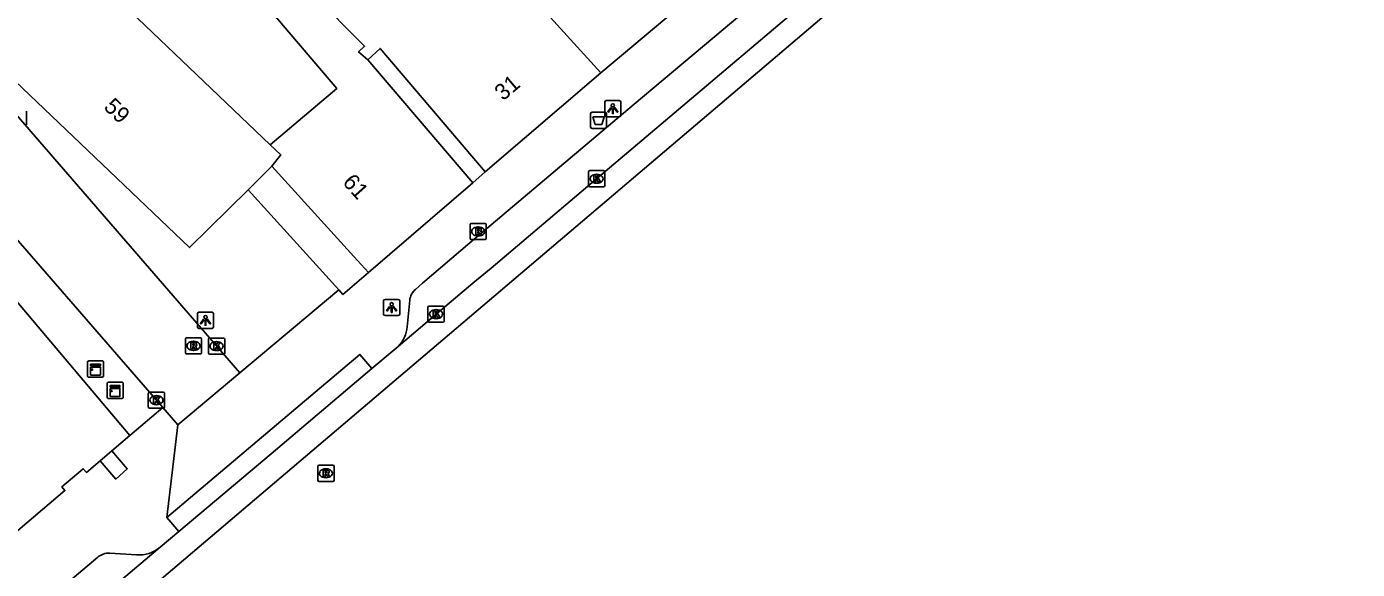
# Model space of a CAD drawing. Extents: x 161772 to 163123, y 383092 to 383917.
# Drawn here: x 162310.8 to 162393, y 383232.3 to 383265.9 of the extents above; entities that cross this region are included whole.
import ezdxf

# ---------------------------------------------------------------- set-up
doc = ezdxf.new("R2010")
doc.units = 0
for name, color, linetype in [('IMGEO_Afvalbak', 7, 'Continuous'), ('IMGEO_Brandkraan', 7, 'Continuous'), ('IMGEO_Kast', 7, 'Continuous'), ('IMGEO_Kolk', 7, 'Continuous'), ('IMGEO_Lichtpunt', 7, 'Continuous'), ('IMGEO_Pand', 7, 'Continuous'), ('IMGEO_Pand_nummerreeks', 7, 'Continuous'), ('IMGEO_Rijbaan_lokaal_gesloten', 7, 'Continuous'), ('IMGEO_Rioolput', 7, 'Continuous'), ('IMGEO_Voetpad_open', 7, 'Continuous')]:
    doc.layers.add(name, color=color, linetype=linetype)

msp = doc.modelspace()

# ---------------------------------------------------------------- linework, layer by layer
at = {"layer": 'IMGEO_Afvalbak'}
for p, q in [((162345.628, 383259.67), (162345.628, 383260.47)), ((162345.628, 383260.47), (162345.628, 383259.67)), ((162345.728, 383260.57), (162346.518, 383260.57)), ((162346.518, 383260.57), (162345.728, 383260.57)), ((162346.618, 383260.47), (162346.618, 383259.67)), ((162346.618, 383259.67), (162346.618, 383260.47)), ((162346.518, 383259.57), (162345.728, 383259.57)), ((162345.728, 383259.57), (162346.518, 383259.57))]:
    msp.add_line(p, q, dxfattribs=at)
msp.add_lwpolyline([(162345.771, 383260.284), (162346.475, 383260.284), (162346.326, 383259.814), (162345.92, 383259.814), (162345.771, 383260.284)], dxfattribs=at)
for centre, start, end in [((162345.728, 383260.47), 90, 180), ((162345.728, 383260.47), 90, 180), ((162346.518, 383260.47), 0, 90), ((162346.518, 383260.47), 360, 90), ((162345.728, 383259.67), 180, 270), ((162345.728, 383259.67), 180, 270), ((162346.518, 383259.67), 270, 0), ((162346.518, 383259.67), 270, 0)]:
    msp.add_arc(centre, 0.1, start, end, dxfattribs=at)
at = {"layer": 'IMGEO_Brandkraan'}
for p, q in [((162338.189, 383252.772), (162338.189, 383253.624)), ((162338.264, 383253.698), (162339.116, 383253.698)), ((162338.677, 383253.478), (162338.702, 383253.478)), ((162339.19, 383253.624), (162339.19, 383252.772)), ((162339.116, 383252.698), (162338.264, 383252.698)), ((162338.7, 383252.918), (162338.675, 383252.918))]:
    msp.add_line(p, q, dxfattribs=at)
for points in [[(162338.189, 383252.772), (162338.189, 383253.624)], [(162338.264, 383253.698), (162339.116, 383253.698)], [(162338.537, 383253.398), (162338.537, 383252.998), (162338.75, 383252.998)], [(162338.768, 383253.398), (162338.537, 383253.398)], [(162338.716, 383253.317), (162338.662, 383253.317), (162338.662, 383253.241)], [(162338.662, 383253.241), (162338.715, 383253.241)], [(162339.19, 383253.624), (162339.19, 383252.772)], [(162339.116, 383252.698), (162338.264, 383252.698)], [(162338.724, 383253.165), (162338.662, 383253.165), (162338.662, 383253.084)], [(162338.662, 383253.084), (162338.724, 383253.084)]]:
    msp.add_lwpolyline(points, dxfattribs=at)
for centre, radius, start, end in [((162338.266, 383253.622), 0.0765, 91.55205, 178.44795), ((162338.266, 383253.622), 0.0765, 91.55205, 178.44795), ((162338.717, 383253.279), 0.0379, 267.82845, 90.93552), ((162338.772, 383253.253), 0.145, 59.4692, 91.53667), ((162338.797, 383253.3), 0.0922, 285.51372, 58.15012), ((162339.114, 383253.622), 0.0765, 1.55205, 88.44795), ((162339.114, 383253.622), 0.0765, 1.55205, 88.44795), ((162338.266, 383252.774), 0.0765, 181.55205, 268.44795), ((162338.266, 383252.774), 0.0765, 181.55205, 268.44795), ((162338.725, 383253.124), 0.0404, 269.87594, 90.50774), ((162338.756, 383253.249), 0.251, 268.66757, 293.53466), ((162338.802, 383253.108), 0.105, 301.31148, 78.98903), ((162339.114, 383252.774), 0.0765, 271.55205, 358.44795), ((162339.114, 383252.774), 0.0765, 271.55205, 358.44795)]:
    msp.add_arc(centre, radius, start, end, dxfattribs=at)
for centre, major_axis, ratio, start_param, end_param in [((162338.676, 383253.198), (-0.387, 0.002), 0.722429, 4.712389, 7.853982), ((162338.701, 383253.198), (-0.39, 0.002), 0.717154, 1.570796, 4.712389)]:
    msp.add_ellipse(centre, major_axis=major_axis, ratio=ratio, start_param=start_param, end_param=end_param, dxfattribs=at)
at = {"layer": 'IMGEO_Kast'}
for p, q in [((162314.555, 383244.276), (162314.555, 383245.117)), ((162314.555, 383245.117), (162314.555, 383244.276)), ((162314.63, 383245.201), (162315.471, 383245.201)), ((162315.471, 383245.201), (162314.63, 383245.201)), ((162315.555, 383245.126), (162315.555, 383244.285)), ((162315.555, 383244.285), (162315.555, 383245.126)), ((162315.48, 383244.201), (162314.639, 383244.201)), ((162314.639, 383244.201), (162315.48, 383244.201)), ((162315.764, 383242.957), (162315.764, 383243.798)), ((162315.764, 383243.798), (162315.764, 383242.957)), ((162315.839, 383243.882), (162316.68, 383243.882)), ((162316.68, 383243.882), (162315.839, 383243.882)), ((162316.764, 383243.807), (162316.764, 383242.966)), ((162316.764, 383242.966), (162316.764, 383243.807)), ((162316.689, 383242.882), (162315.848, 383242.882)), ((162315.848, 383242.882), (162316.689, 383242.882))]:
    msp.add_line(p, q, dxfattribs=at)
for points in [[(162314.75, 383244.991), (162315.35, 383244.991), (162315.35, 383244.906), (162314.75, 383244.906), (162314.75, 383244.991)], [(162314.75, 383244.816), (162315.35, 383244.816), (162315.35, 383244.327), (162314.75, 383244.327), (162314.75, 383244.816)], [(162315.959, 383243.672), (162316.559, 383243.672), (162316.559, 383243.587), (162315.959, 383243.587), (162315.959, 383243.672)], [(162315.959, 383243.497), (162316.559, 383243.497), (162316.559, 383243.008), (162315.959, 383243.008), (162315.959, 383243.497)]]:
    msp.add_lwpolyline(points, dxfattribs=at)
for centre in [(162314.834, 383244.665), (162316.043, 383243.346)]:
    msp.add_circle(centre, 0.0377, dxfattribs=at)
for centre, start, end in [((162314.633, 383245.123), 92.4484, 184.28452), ((162314.633, 383245.123), 92.4484, 184.28452), ((162315.477, 383245.123), 2.4484, 94.28452), ((162315.477, 383245.123), 2.4484, 94.28452), ((162314.633, 383244.279), 182.4484, 274.28452), ((162314.633, 383244.279), 182.4484, 274.28452), ((162315.477, 383244.279), 272.4484, 4.28452), ((162315.477, 383244.279), 272.4484, 4.28452), ((162315.842, 383243.804), 92.4484, 184.28452), ((162315.842, 383243.804), 92.4484, 184.28452), ((162316.686, 383243.804), 2.4484, 94.28452), ((162316.686, 383243.804), 2.4484, 94.28452), ((162315.842, 383242.96), 182.4484, 274.28452), ((162315.842, 383242.96), 182.4484, 274.28452), ((162316.686, 383242.96), 272.4484, 4.28452), ((162316.686, 383242.96), 272.4484, 4.28452)]:
    msp.add_arc(centre, 0.0779, start, end, dxfattribs=at)
at = {"layer": 'IMGEO_Kolk'}
for p, q in [((162310.795, 383260.632), (162310.795, 383259.78)), ((162345.508, 383256.032), (162345.508, 383256.884)), ((162345.583, 383256.958), (162346.435, 383256.958)), ((162345.996, 383256.738), (162346.021, 383256.738)), ((162346.509, 383256.884), (162346.509, 383256.032)), ((162346.435, 383255.958), (162345.583, 383255.958)), ((162346.019, 383256.178), (162345.994, 383256.178)), ((162335.588, 383247.665), (162335.588, 383248.517)), ((162335.663, 383248.591), (162336.515, 383248.591)), ((162336.076, 383248.371), (162336.101, 383248.371)), ((162336.589, 383248.517), (162336.589, 383247.665)), ((162336.515, 383247.591), (162335.663, 383247.591)), ((162336.099, 383247.811), (162336.074, 383247.811)), ((162322.031, 383245.689), (162322.031, 383246.541)), ((162322.106, 383246.615), (162322.958, 383246.615)), ((162322.542, 383245.835), (162322.517, 383245.835)), ((162322.519, 383246.395), (162322.544, 383246.395)), ((162323.032, 383246.541), (162323.032, 383245.689)), ((162322.958, 383245.615), (162322.106, 383245.615)), ((162318.313, 383242.35), (162318.313, 383243.202)), ((162318.388, 383243.276), (162319.24, 383243.276)), ((162318.801, 383243.056), (162318.826, 383243.056)), ((162319.314, 383243.202), (162319.314, 383242.35)), ((162319.24, 383242.276), (162318.388, 383242.276)), ((162318.824, 383242.496), (162318.799, 383242.496))]:
    msp.add_line(p, q, dxfattribs=at)
for points in [[(162310.795, 383260.632), (162310.795, 383259.78)], [(162345.508, 383256.032), (162345.508, 383256.884)], [(162345.583, 383256.958), (162346.435, 383256.958)], [(162345.829, 383256.658), (162345.952, 383256.658), (162345.952, 383256.507), (162346.082, 383256.658), (162346.246, 383256.658), (162346.1, 383256.507), (162346.253, 383256.258), (162346.101, 383256.258), (162346.016, 383256.422), (162345.952, 383256.355), (162345.952, 383256.258), (162345.829, 383256.258), (162345.829, 383256.658)], [(162346.509, 383256.884), (162346.509, 383256.032)], [(162346.435, 383255.958), (162345.583, 383255.958)], [(162335.588, 383247.665), (162335.588, 383248.517)], [(162335.663, 383248.591), (162336.515, 383248.591)], [(162335.909, 383248.291), (162336.032, 383248.291), (162336.032, 383248.14), (162336.162, 383248.291), (162336.326, 383248.291), (162336.18, 383248.14), (162336.333, 383247.891), (162336.181, 383247.891), (162336.096, 383248.055), (162336.032, 383247.988), (162336.032, 383247.891), (162335.909, 383247.891), (162335.909, 383248.291)], [(162336.589, 383248.517), (162336.589, 383247.665)], [(162336.515, 383247.591), (162335.663, 383247.591)], [(162322.031, 383245.689), (162322.031, 383246.541)], [(162322.106, 383246.615), (162322.958, 383246.615)], [(162322.352, 383246.315), (162322.475, 383246.315), (162322.475, 383246.164), (162322.605, 383246.315), (162322.769, 383246.315), (162322.623, 383246.164), (162322.776, 383245.915), (162322.624, 383245.915), (162322.539, 383246.079), (162322.475, 383246.012), (162322.475, 383245.915), (162322.352, 383245.915), (162322.352, 383246.315)], [(162323.032, 383246.541), (162323.032, 383245.689)], [(162322.958, 383245.615), (162322.106, 383245.615)], [(162318.313, 383242.35), (162318.313, 383243.202)], [(162318.388, 383243.276), (162319.24, 383243.276)], [(162318.634, 383242.976), (162318.757, 383242.976), (162318.757, 383242.825), (162318.887, 383242.976), (162319.051, 383242.976), (162318.905, 383242.825), (162319.058, 383242.576), (162318.906, 383242.576), (162318.821, 383242.74), (162318.757, 383242.673), (162318.757, 383242.576), (162318.634, 383242.576), (162318.634, 383242.976)], [(162319.314, 383243.202), (162319.314, 383242.35)], [(162319.24, 383242.276), (162318.388, 383242.276)]]:
    msp.add_lwpolyline(points, dxfattribs=at)
for centre, start, end in [((162345.585, 383256.882), 91.55205, 178.44795), ((162345.585, 383256.882), 91.55205, 178.44795), ((162346.433, 383256.882), 1.55205, 88.44795), ((162346.433, 383256.882), 1.55205, 88.44795), ((162345.585, 383256.034), 181.55205, 268.44795), ((162345.585, 383256.034), 181.55205, 268.44795), ((162346.433, 383256.034), 271.55205, 358.44795), ((162346.433, 383256.034), 271.55205, 358.44795), ((162335.665, 383248.515), 91.55205, 178.44795), ((162335.665, 383248.515), 91.55205, 178.44795), ((162336.513, 383248.515), 1.55205, 88.44795), ((162336.513, 383248.515), 1.55205, 88.44795), ((162335.665, 383247.667), 181.55205, 268.44795), ((162335.665, 383247.667), 181.55205, 268.44795), ((162336.513, 383247.667), 271.55205, 358.44795), ((162336.513, 383247.667), 271.55205, 358.44795), ((162322.108, 383246.539), 91.55205, 178.44795), ((162322.108, 383246.539), 91.55205, 178.44795), ((162322.956, 383246.539), 1.55205, 88.44795), ((162322.956, 383246.539), 1.55205, 88.44795), ((162322.108, 383245.691), 181.55205, 268.44795), ((162322.108, 383245.691), 181.55205, 268.44795), ((162322.956, 383245.691), 271.55205, 358.44795), ((162322.956, 383245.691), 271.55205, 358.44795), ((162318.39, 383243.2), 91.55205, 178.44795), ((162318.39, 383243.2), 91.55205, 178.44795), ((162319.238, 383243.2), 1.55205, 88.44795), ((162319.238, 383243.2), 1.55205, 88.44795), ((162318.39, 383242.352), 181.55205, 268.44795), ((162318.39, 383242.352), 181.55205, 268.44795), ((162319.238, 383242.352), 271.55205, 358.44795), ((162319.238, 383242.352), 271.55205, 358.44795)]:
    msp.add_arc(centre, 0.0765, start, end, dxfattribs=at)
for centre, major_axis, ratio, start_param, end_param in [((162345.995, 383256.458), (-0.387, 0.002), 0.722429, 4.712389, 7.853982), ((162346.02, 383256.458), (-0.39, 0.002), 0.717154, 1.570796, 4.712389), ((162336.075, 383248.091), (-0.387, 0.002), 0.722429, 4.712389, 7.853982), ((162336.1, 383248.091), (-0.39, 0.002), 0.717154, 1.570796, 4.712389), ((162322.518, 383246.115), (-0.387, 0.002), 0.722429, 4.712389, 7.853982), ((162322.543, 383246.115), (-0.39, 0.002), 0.717154, 1.570796, 4.712389), ((162318.8, 383242.776), (-0.387, 0.002), 0.722429, 4.712389, 7.853982), ((162318.825, 383242.776), (-0.39, 0.002), 0.717154, 1.570796, 4.712389)]:
    msp.add_ellipse(centre, major_axis=major_axis, ratio=ratio, start_param=start_param, end_param=end_param, dxfattribs=at)
at = {"layer": 'IMGEO_Lichtpunt'}
for p, q in [((162346.508, 383261.193), (162346.508, 383260.386)), ((162346.508, 383261.193), (162346.508, 383260.386)), ((162347.41, 383261.288), (162346.602, 383261.288)), ((162347.41, 383261.288), (162346.602, 383261.288)), ((162347.504, 383260.386), (162347.504, 383261.193)), ((162347.504, 383260.386), (162347.504, 383261.193)), ((162346.602, 383260.292), (162347.41, 383260.292)), ((162346.602, 383260.292), (162347.41, 383260.292)), ((162332.845, 383248.905), (162332.845, 383248.098)), ((162332.845, 383248.905), (162332.845, 383248.098)), ((162333.747, 383249), (162332.939, 383249)), ((162333.747, 383249), (162332.939, 383249)), ((162333.841, 383248.098), (162333.841, 383248.905)), ((162333.841, 383248.098), (162333.841, 383248.905)), ((162321.349, 383248.109), (162321.349, 383247.302)), ((162321.349, 383248.109), (162321.349, 383247.302)), ((162322.251, 383248.204), (162321.443, 383248.204)), ((162322.251, 383248.204), (162321.443, 383248.204)), ((162322.345, 383247.302), (162322.345, 383248.109)), ((162322.345, 383247.302), (162322.345, 383248.109)), ((162332.939, 383248.004), (162333.747, 383248.004)), ((162332.939, 383248.004), (162333.747, 383248.004)), ((162321.443, 383247.208), (162322.251, 383247.208)), ((162321.443, 383247.208), (162322.251, 383247.208))]:
    msp.add_line(p, q, dxfattribs=at)
for points in [[(162346.882, 383260.857), (162346.921, 383260.829), (162346.733, 383260.567), (162346.695, 383260.594), (162346.882, 383260.857)], [(162346.984, 383260.809), (162347.031, 383260.809), (162347.031, 383260.487), (162346.984, 383260.487), (162346.984, 383260.809)], [(162347.094, 383260.829), (162347.132, 383260.856), (162347.319, 383260.594), (162347.28, 383260.566), (162347.094, 383260.829)], [(162333.219, 383248.569), (162333.258, 383248.541), (162333.07, 383248.279), (162333.032, 383248.306), (162333.219, 383248.569)], [(162333.321, 383248.521), (162333.368, 383248.521), (162333.368, 383248.199), (162333.321, 383248.199), (162333.321, 383248.521)], [(162333.431, 383248.541), (162333.469, 383248.568), (162333.656, 383248.306), (162333.617, 383248.278), (162333.431, 383248.541)], [(162321.723, 383247.773), (162321.762, 383247.745), (162321.574, 383247.483), (162321.536, 383247.51), (162321.723, 383247.773)], [(162321.825, 383247.725), (162321.872, 383247.725), (162321.872, 383247.403), (162321.825, 383247.403), (162321.825, 383247.725)], [(162321.935, 383247.745), (162321.973, 383247.772), (162322.16, 383247.51), (162322.121, 383247.482), (162321.935, 383247.745)]]:
    msp.add_lwpolyline(points, dxfattribs=at)
for centre in [(162347.007, 383260.991), (162333.344, 383248.703), (162321.848, 383247.907)]:
    msp.add_circle(centre, 0.0994, dxfattribs=at)
for centre, start, end in [((162346.602, 383261.193), 90, 180), ((162346.602, 383261.193), 90, 180), ((162347.41, 383261.193), 0, 90), ((162347.41, 383261.193), 0, 90), ((162346.602, 383260.386), 180, 270), ((162346.602, 383260.386), 180, 270), ((162347.41, 383260.386), 270, 0), ((162347.41, 383260.386), 270, 360), ((162332.939, 383248.905), 90, 180), ((162332.939, 383248.905), 90, 180), ((162333.747, 383248.905), 0, 90), ((162333.747, 383248.905), 0, 90), ((162321.443, 383248.109), 90, 180), ((162321.443, 383248.109), 90, 180), ((162322.251, 383248.109), 0, 90), ((162322.251, 383248.109), 0, 90), ((162332.939, 383248.098), 180, 270), ((162332.939, 383248.098), 180, 270), ((162333.747, 383248.098), 270, 0), ((162333.747, 383248.098), 270, 360), ((162321.443, 383247.302), 180, 270), ((162321.443, 383247.302), 180, 270), ((162322.251, 383247.302), 270, 0), ((162322.251, 383247.302), 270, 360)]:
    msp.add_arc(centre, 0.0946, start, end, dxfattribs=at)
at = {"layer": 'IMGEO_Pand'}
for points in [[(162346.265, 383262.997), (162338.57, 383271.481), (162338.004, 383271.019), (162333.008, 383275.992)], [(162325.846, 383258.547), (162329.957, 383262.04), (162323.454, 383269.69), (162325.199, 383271.174), (162325.303, 383271.069)], [(162331.866, 383263.812), (162331.304, 383264.297), (162331.67, 383264.649), (162325.303, 383271.069)], [(162312.965, 383269.713), (162313.561, 383270.296), (162325.846, 383258.547)], [(162351.614, 383267.518), (162346.265, 383262.997)], [(162324.476, 383255.781), (162320.866, 383252.207), (162308.268, 383264.195)], [(162331.866, 383263.812), (162332.636, 383264.517), (162339.126, 383256.895)], [(162338.354, 383256.203), (162331.866, 383263.812)], [(162346.265, 383262.997), (162339.126, 383256.895)], [(162325.846, 383258.547), (162326.5, 383257.928), (162325.949, 383257.238)], [(162325.949, 383257.238), (162324.476, 383255.781)], [(162331.911, 383250.664), (162331.007, 383251.661), (162325.949, 383257.238)], [(162338.354, 383256.203), (162331.911, 383250.664)], [(162307.174, 383252.434), (162317.179, 383240.601)], [(162316.056, 383239.645), (162317.179, 383240.601)], [(162315.334, 383239.031), (162316.056, 383239.645)], [(162305.188, 383230.428), (162308.505, 383233.243), (162308.311, 383233.472), (162309.639, 383234.596), (162309.833, 383234.367), (162313.158, 383237.185), (162312.964, 383237.414), (162314.291, 383238.537), (162314.486, 383238.309), (162315.334, 383239.031)]]:
    msp.add_lwpolyline(points, dxfattribs=at)
at = {"layer": 'IMGEO_Rijbaan_lokaal_gesloten'}
for points in [[(162501.18, 383386.596), (162499.827, 383385.459), (162477.128, 383365.985), (162459.036, 383350.651), (162175.227, 383109.464), (162171.607, 383105.25), (162169.364, 383100.909), (162168.706, 383099.067), (162168.602, 383098.586)], [(162333.755, 383246.101), (162336.091, 383248.087), (162338.371, 383250), (162339.489, 383250.937), (162346.009, 383256.458), (162358.661, 383267.166), (162361.825, 383269.852), (162371.447, 383277.945), (162376.27, 383282.045), (162386.657, 383290.883), (162388.29, 383292.272), (162389.114, 383292.973)], [(162332.127, 383244.723), (162333.493, 383245.878), (162333.755, 383246.101)], [(162320.2, 383234.655), (162325.904, 383239.465), (162332.127, 383244.723)], [(162320.2, 383234.655), (162319.047, 383233.682)], [(162276.765, 383198.05), (162277.016, 383198.26), (162285.931, 383205.773), (162293.943, 383212.532), (162301.935, 383219.268), (162309.075, 383225.29), (162316.264, 383231.344), (162319.047, 383233.682)]]:
    msp.add_lwpolyline(points, dxfattribs=at)
at = {"layer": 'IMGEO_Rioolput'}
for p, q in [((162320.606, 383245.707), (162320.606, 383246.559)), ((162320.681, 383246.633), (162321.533, 383246.633)), ((162321.117, 383245.853), (162321.092, 383245.853)), ((162321.094, 383246.413), (162321.119, 383246.413)), ((162321.607, 383246.559), (162321.607, 383245.707)), ((162321.533, 383245.633), (162320.681, 383245.633)), ((162328.786, 383237.83), (162328.786, 383238.682)), ((162328.861, 383238.756), (162329.713, 383238.756)), ((162329.274, 383238.536), (162329.299, 383238.536)), ((162329.787, 383238.682), (162329.787, 383237.83)), ((162329.713, 383237.756), (162328.861, 383237.756)), ((162329.297, 383237.976), (162329.272, 383237.976))]:
    msp.add_line(p, q, dxfattribs=at)
for points in [[(162320.606, 383245.707), (162320.606, 383246.559)], [(162320.681, 383246.633), (162321.533, 383246.633)], [(162321.195, 383246.331), (162320.943, 383246.333), (162320.943, 383245.933)], [(162320.943, 383245.933), (162321.067, 383245.933), (162321.067, 383246.095), (162321.078, 383246.095)], [(162321.121, 383246.252), (162321.067, 383246.252), (162321.067, 383246.171)], [(162321.067, 383246.171), (162321.119, 383246.171)], [(162321.125, 383246.066), (162321.196, 383245.933), (162321.336, 383245.933), (162321.271, 383246.059)], [(162321.607, 383246.559), (162321.607, 383245.707)], [(162321.533, 383245.633), (162320.681, 383245.633)], [(162328.786, 383237.83), (162328.786, 383238.682)], [(162328.861, 383238.756), (162329.713, 383238.756)], [(162329.375, 383238.454), (162329.123, 383238.456), (162329.123, 383238.056)], [(162329.787, 383238.682), (162329.787, 383237.83)], [(162329.713, 383237.756), (162328.861, 383237.756)], [(162329.123, 383238.056), (162329.247, 383238.056), (162329.247, 383238.218), (162329.258, 383238.218)], [(162329.301, 383238.375), (162329.247, 383238.375), (162329.247, 383238.294)], [(162329.247, 383238.294), (162329.299, 383238.294)], [(162329.305, 383238.189), (162329.376, 383238.056), (162329.516, 383238.056), (162329.451, 383238.182)]]:
    msp.add_lwpolyline(points, dxfattribs=at)
for centre, radius, start, end in [((162320.683, 383246.557), 0.0765, 91.55205, 178.44795), ((162320.683, 383246.557), 0.0765, 91.55205, 178.44795), ((162321.077, 383246.042), 0.0533, 26.02933, 88.69889), ((162321.103, 383246.36), 0.19, 274.7715, 282.96867), ((162321.127, 383246.156), 0.0964, 77.00612, 93.18647), ((162321.141, 383246.213), 0.0378, 276.66336, 79.67722), ((162321.194, 383246.221), 0.109, 350.36119, 89.41601), ((162321.192, 383246.221), 0.112, 277.58423, 350.98172), ((162321.176, 383246.006), 0.108, 29.51342, 73.79051), ((162321.531, 383246.557), 0.0765, 1.55205, 88.44795), ((162321.531, 383246.557), 0.0765, 1.55205, 88.44795), ((162320.683, 383245.709), 0.0765, 181.55205, 268.44795), ((162320.683, 383245.709), 0.0765, 181.55205, 268.44795), ((162321.531, 383245.709), 0.0765, 271.55205, 358.44795), ((162321.531, 383245.709), 0.0765, 271.55205, 358.44795), ((162328.863, 383238.68), 0.0765, 91.55205, 178.44795), ((162328.863, 383238.68), 0.0765, 91.55205, 178.44795), ((162329.374, 383238.344), 0.109, 350.36119, 89.41601), ((162329.711, 383238.68), 0.0765, 1.55205, 88.44795), ((162329.711, 383238.68), 0.0765, 1.55205, 88.44795), ((162328.863, 383237.832), 0.0765, 181.55205, 268.44795), ((162328.863, 383237.832), 0.0765, 181.55205, 268.44795), ((162329.257, 383238.165), 0.0533, 26.02933, 88.69889), ((162329.283, 383238.483), 0.19, 274.7715, 282.96867), ((162329.307, 383238.279), 0.0964, 77.00612, 93.18647), ((162329.321, 383238.336), 0.0378, 276.66336, 79.67722), ((162329.372, 383238.344), 0.112, 277.58423, 350.98172), ((162329.356, 383238.129), 0.108, 29.51342, 73.79051), ((162329.711, 383237.832), 0.0765, 271.55205, 358.44795), ((162329.711, 383237.832), 0.0765, 271.55205, 358.44795)]:
    msp.add_arc(centre, radius, start, end, dxfattribs=at)
for centre, major_axis, ratio, start_param, end_param in [((162321.093, 383246.133), (-0.387, 0.002), 0.722429, 4.712389, 7.853982), ((162321.118, 383246.133), (-0.39, 0.002), 0.717154, 1.570796, 4.712389), ((162329.273, 383238.256), (-0.387, 0.002), 0.722429, 4.712389, 7.853982), ((162329.298, 383238.256), (-0.39, 0.002), 0.717154, 1.570796, 4.712389)]:
    msp.add_ellipse(centre, major_axis=major_axis, ratio=ratio, start_param=start_param, end_param=end_param, dxfattribs=at)
at = {"layer": 'IMGEO_Voetpad_open'}
for points in [[(162334.814, 383249.62), (162335.261, 383250), (162338.185, 383252.49), (162348.336, 383261.062), (162356.259, 383267.741), (162358.541, 383269.679), (162362.316, 383272.868), (162366.246, 383276.167), (162373.871, 383282.628)], [(162323.973, 383244.46), (162307.468, 383263.492)], [(162303.222, 383260.718), (162319.205, 383242.326)], [(162339.126, 383256.895), (162338.354, 383256.203)], [(162330.077, 383249.586), (162324.476, 383255.781)], [(162331.911, 383250.664), (162330.334, 383249.303), (162330.077, 383249.586)], [(162330.077, 383249.586), (162323.973, 383244.46)], [(162334.3, 383247.314), (162334.46, 383248.954)], [(162319.458, 383235.533), (162328.629, 383243.275), (162331.386, 383245.602), (162332.127, 383244.723)], [(162323.973, 383244.46), (162320.145, 383241.245)], [(162317.179, 383240.601), (162319.205, 383242.326)], [(162319.205, 383242.326), (162320.145, 383241.245)], [(162320.145, 383241.245), (162319.458, 383235.533)], [(162315.334, 383239.031), (162316.298, 383237.899), (162317.011, 383238.524), (162316.056, 383239.645)], [(162319.458, 383235.533), (162320.2, 383234.655)], [(162315.187, 383233.063), (162305.208, 383224.657)], [(162317.588, 383233.208), (162315.927, 383233.325)]]:
    msp.add_lwpolyline(points, dxfattribs=at)
for centre, radius, start, end in [((162335.563, 383248.795), 1.114, 132.22359, 171.7923), ((162332.385, 383247.445), 1.919, 315.53738, 356.07392), ((162317.709, 383235.319), 2.114, 266.72582, 309.27007), ((162315.901, 383232.221), 1.104, 88.6762, 130.31723)]:
    msp.add_arc(centre, radius, start, end, dxfattribs=at)

# ---------------------------------------------------------------- texts
at = {"layer": 'IMGEO_Pand_nummerreeks'}
for s, rotation, p in [('31', 40.14543, (162340.229, 383261.235)), ('59', 316.02204, (162315.506, 383260.826)), ('61', 311.89722, (162330.264, 383256.204))]:
    msp.add_text(s, height=1, rotation=rotation, dxfattribs=at).set_placement(p)

doc.saveas('drawing.dxf')
